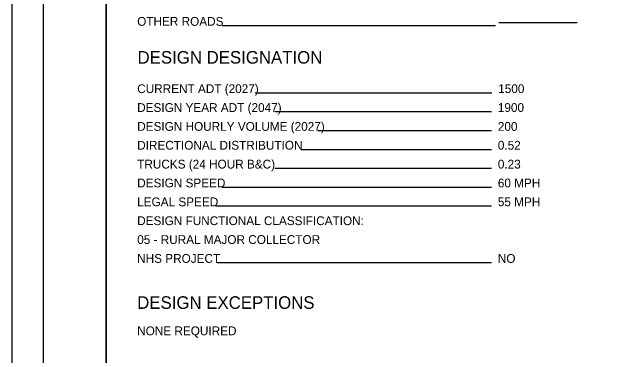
# Model space of a CAD drawing. Extents: x 0 to 39.4, y 0 to 22.
# Drawn here: x 0 to 9.51, y 5.64 to 11.1 of the extents above; entities that cross this region are included whole.
import ezdxf

# ---------------------------------------------------------------- set-up
doc = ezdxf.new("R2010")
doc.units = 0
for name, color, linetype in [('SH_Border', 7, 'Continuous'), ('SH_Cut_Line', 7, 'Continuous'), ('SH_Data', 7, 'Continuous'), ('SH_Text', 7, 'Continuous')]:
    doc.layers.add(name, color=color, linetype=linetype)

msp = doc.modelspace()

# ---------------------------------------------------------------- linework, layer by layer
at = {"layer": 'SH_Border'}
for points in [[(0.5, 21.5), (1.5, 21.5), (1.5, 0.5), (0.5, 0.5)], [(1.5, 21.5), (33.5, 21.5), (33.5, 0.5), (1.5, 0.5)]]:
    msp.add_lwpolyline(points, close=True, dxfattribs=at)
at = {"layer": 'SH_Cut_Line'}
msp.add_lwpolyline([(0, 0), (34, 0), (34, 22), (0, 22)], close=True, dxfattribs=at)
at = {"layer": 'SH_Data'}
for p, q in [((7.7, 10.8767), (3.3471, 10.8767)), ((9, 10.9223), (7.75, 10.9223)), ((7.6424, 9.8062), (3.871, 9.8062)), ((7.6368, 9.5062), (4.1885, 9.5062)), ((7.6368, 9.2062), (4.8723, 9.2062)), ((7.6368, 8.9062), (4.6037, 8.9062)), ((7.6368, 8.6062), (4.1885, 8.6062)), ((7.6368, 8.3062), (3.346, 8.3062)), ((7.6368, 8.0062), (3.2422, 8.0062)), ((7.6368, 7.1062), (3.2669, 7.1062))]:
    msp.add_line(p, q, dxfattribs=at)

# ---------------------------------------------------------------- texts
msp.add_text('DESIGN DESIGNATION', height=0.2, dxfattribs=at).set_placement((2, 10.2747))
at = {"layer": 'SH_Text'}
for s, height, p in [('OTHER ROADS', 0.14, (1.9944, 10.8767)), ('CURRENT ADT (2027)', 0.14, (1.9944, 9.8062)), ('1500', 0.14, (7.7424, 9.8062)), ('DESIGN YEAR ADT (2047)', 0.14, (1.9944, 9.5062)), ('1900', 0.14, (7.7368, 9.5062)), ('DESIGN HOURLY VOLUME (2027)', 0.14, (1.9944, 9.2062)), ('200', 0.14, (7.7368, 9.2062)), ('DIRECTIONAL DISTRIBUTION', 0.14, (1.9944, 8.9062)), ('0.52', 0.14, (7.7368, 8.9062)), ('TRUCKS (24 HOUR B&C)', 0.14, (1.9944, 8.6062)), ('0.23', 0.14, (7.7368, 8.6062)), ('DESIGN SPEED', 0.14, (1.9944, 8.3062)), ('60 MPH', 0.14, (7.7368, 8.3062)), ('LEGAL SPEED', 0.14, (1.9944, 8.0062)), ('55 MPH', 0.14, (7.7368, 8.0062)), ('DESIGN FUNCTIONAL CLASSIFICATION:', 0.14, (1.9944, 7.7062)), ('05 - RURAL MAJOR COLLECTOR', 0.14, (1.9944, 7.4062)), ('NHS PROJECT', 0.14, (1.9944, 7.1062)), ('NO', 0.14, (7.7368, 7.1062)), ('DESIGN EXCEPTIONS', 0.2, (1.9944, 6.3744)), ('NONE REQUIRED ', 0.14, (1.9944, 5.9544))]:
    msp.add_text(s, height=height, dxfattribs=at).set_placement(p)

doc.saveas('drawing.dxf')
